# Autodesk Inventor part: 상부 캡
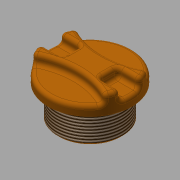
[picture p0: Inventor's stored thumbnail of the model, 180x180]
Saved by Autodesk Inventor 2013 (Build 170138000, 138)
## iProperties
Created: 2016-09
Part Number: 상부 캡
Material: ABS 플라스틱
Document SubType Name: Modeling
Designer: mduedu
Density: 1.493 g/cm^3
Mass: 32.6939 g
Surface Area: 67.9045 cm^2
Volume: 21.8981 cm^3
Author: mduedu
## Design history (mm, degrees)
sketch "스케치1"
  geometry: C1 r 22.5 at (0, 0); 1 further point
  constraints: 1 centre point, 1 coincident
  dimensions: "d0" = 45 diameter of C1
extrude "돌출1" new body sketch "스케치1" distance "d1" = 10; taper "d2" = 0 deg
sketch "스케치2" dims "d4" = 80
  geometry: C1 r 22.5 at (0, 0) reference; 3 further points
  constraints: 3 vertical alignment, 2 other
  dimensions: "d3" = 7 distance of point (0, 7) point (0, 0)
extrude "돌출2" cut sketch "스케치2" distance "d5" = 5; taper "d6" = 0 deg
sketch "스케치3"
  geometry: L1 (-22.5, 0)-(0, 0); L2 (-21.937, 5)-(-10, 5); L3 (-10, 5)-(-10, -5); L4 (-10, -5)-(-21.937, -5); A1 r 22.5 centre (0, 0) between (-19.118, 11.864) and (-19.118, -11.864) reference; A2 r 22.5 centre (0, 0) between (-21.937, 5) and (-21.937, -5); 1 further point
  constraints: 8 end point, 5 point on circle, 2 horizontal, 1 centre point, 1 coincident, 1 parallel, 1 perpendicular, 1 symmetric about line
  dimensions: "d7" = 10 distance from line of L3 point (0, 0); "d8" = 10 distance of L2.end L3.end
extrude "돌출3" cut sketch "스케치3" distance "d9" = 5; taper "d10" = 0 deg
fillet "모깎기1" dims "d11" = 2
fillet "모깎기2" dims "d12" = 2
fillet "모깎기3" dims "d13" = 2
sketch "스케치4"
  geometry: C1 r 17.5 at (0, 0); 1 further point
  constraints: 1 centre point, 1 coincident
  dimensions: "d14" = 35 diameter of C1
extrude "돌출4" join sketch "스케치4" distance "d15" = 17; taper "d16" = 0 deg
sketch "스케치5"
  geometry: C1 r 12.5 at (0, 0); 1 further point
  constraints: 1 centre point, 1 coincident
  dimensions: "d17" = 25 diameter of C1
extrude "돌출5" cut sketch "스케치5" distance "d18" = 10; taper "d19" = 0 deg
fillet "모깎기4" dims "d20" = 3
sketch "스케치6"
  geometry: L1 (0, 22.5)-(0, -22.5) reference; L2 (0, 17.5)-(-1, 17.5); L3 (-1, 17.5)-(-1, 16.5); L4 (-1, 16.5)-(0, 16.5); L5 (0, 16.5)-(0, 17.5); L6 (0, 17.5)-(-17, 17.5) reference; L7 (-22.401, 0)-(15.404, 0) reference; 1 further point
  constraints: 8 end point, 2 parallel, 1 collinear, 1 horizontal, 1 perpendicular, 1 point on line
  dimensions: "d26" = 1 distance of L2.start L2.end; "d28" = 1 distance of L2.end L3.end
revolve "회전1" sketch "스케치6" stored, may be unused: angle "d29" = 90 deg
feature "스레드1" dims "d21" = 10, "d22" = 0
chamfer "모따기1" distance "d23" = 1; stored, may be unused: second distance "d24" = 2, angle "d25" = 45 deg
chamfer "모따기2" distance "d30" = 1; stored, may be unused: second distance "d31" = 2, angle "d32" = 45 deg
node "솔리드1"
mirror "대칭1"
mirror "대칭2"
node "투영된 루프1"
